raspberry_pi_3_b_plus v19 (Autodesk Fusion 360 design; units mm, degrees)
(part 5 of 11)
sketch "Sketch2" plane through (0, 0, 13.8) normal (0, 0, 1) x axis (-1, 0.0001, 0)
  line L1 (6.9604, -3.1991) -> (6.9605, -3.7992)
  line L2 (3.5604, -3.1996) -> (6.9604, -3.1991)
  line L3 (3.5605, -3.7996) -> (3.5604, -3.1996)
  line L4 (6.9605, -3.7992) -> (3.5605, -3.7996)
  line L5 (7.5605, -3.7991) -> (7.5604, -3.1991)
  line L6 (2.7854, -4.1587) -> (2.7354, -4.1587)
  line L7 (3.9604, -4.0649) -> (3.9604, -4.1089)
  line L8 (2.1854, -4.1587) -> (1.4604, -4.1587)
  line L9 (2.9747, -4.2241) -> (2.8668, -4.176)
  line L10 (3.8604, -4.2089) -> (3.528, -4.2089)
  line L11 (3.4515, -4.2241) -> (2.9747, -4.2241)
  line L12 (1.4604, -4.1587) -> (1.4604, -2.8394)
  line L13 (7.5604, -3.4991) -> (1.4604, -3.4991)
  line L14 (6.9605, -3.7992) -> (3.5605, -3.7996)
  line L15 (2.1854, -2.8394) -> (1.4604, -2.8394)
  line L16 (2.7854, -2.8394) -> (2.7354, -2.8394)
  line L17 (2.9747, -2.7741) -> (2.8668, -2.8221)
  line L18 (3.4515, -2.7741) -> (2.9747, -2.7741)
  line L19 (3.8604, -2.7893) -> (3.528, -2.7893)
  line L20 (3.9604, -2.9332) -> (3.9604, -2.8893)
  line L21 (1.3604, -4.1319) -> (1.0901, -3.9759)
  line L22 (1.4604, -4.1587) -> (1.4604, -4.1587)
  line L23 (0.45, -3.9491) -> (0.9901, -3.9491)
  line L24 (1.3604, -2.8662) -> (1.0901, -3.0223)
  line L25 (0.9901, -3.9491) -> (0.9901, -3.0491)
  line L26 (3.5605, -3.7996) -> (3.5604, -3.1996)
  line L27 (0.8339, -4.1587) -> (1.4604, -4.1587)
  line L28 (0.8339, -2.8339) -> (0.8339, -4.1587)
  line L29 (1.4604, -2.8394) -> (0.8339, -2.8339)
  arc A1 centre (3.528, -4.4089) radius 0.2 clockwise from (3.4515, -4.2241) to (3.528, -4.2089)
  arc A2 centre (4.2269, -3.6495) radius 0.15 clockwise from (4.2269, -3.7995) to (4.1436, -3.7743)
  arc A3 centre (4.0604, -3.8991) radius 0.15 clockwise from (3.9354, -3.982) to (4.1436, -3.7743)
  arc A4 centre (3.8104, -4.0649) radius 0.15 clockwise from (3.9354, -3.982) to (3.9604, -4.0649)
  arc A5 centre (3.8604, -4.1089) radius 0.1 clockwise from (3.9604, -4.1089) to (3.8604, -4.2089)
  arc A6 centre (2.7854, -4.3587) radius 0.2 clockwise from (2.7854, -4.1587) to (2.8668, -4.176)
  arc A7 centre (2.7354, -4.3587) radius 0.2 clockwise from (2.5979, -4.2135) to (2.7354, -4.1587)
  arc A8 centre (2.4604, -4.0683) radius 0.2 clockwise from (2.5979, -4.2135) to (2.3229, -4.2135)
  arc A9 centre (2.1854, -4.3587) radius 0.2 clockwise from (2.1854, -4.1587) to (2.3229, -4.2135)
  arc A10 centre (2.1854, -2.6394) radius 0.2 clockwise from (2.3229, -2.7847) to (2.1854, -2.8394)
  arc A11 centre (2.7354, -2.6394) radius 0.2 clockwise from (2.7354, -2.8394) to (2.5979, -2.7847)
  arc A12 centre (2.7854, -2.6394) radius 0.2 clockwise from (2.8668, -2.8221) to (2.7854, -2.8394)
  arc A13 centre (3.528, -2.5893) radius 0.2 clockwise from (3.528, -2.7893) to (3.4515, -2.7741)
  arc A14 centre (3.8604, -2.8893) radius 0.1 clockwise from (3.8604, -2.7893) to (3.9604, -2.8893)
  arc A15 centre (3.8104, -2.9332) radius 0.15 clockwise from (3.9604, -2.9332) to (3.9354, -3.0162)
  arc A16 centre (4.0604, -3.0991) radius 0.15 clockwise from (4.1436, -3.2239) to (3.9354, -3.0162)
  arc A17 centre (4.2269, -3.3487) radius 0.15 clockwise from (4.1436, -3.2239) to (4.2269, -3.1987)
  arc A18 centre (2.4604, -2.9299) radius 0.2 clockwise from (2.3229, -2.7847) to (2.5979, -2.7847)
  arc A19 centre (1.4604, -3.9587) radius 0.2 clockwise from (1.4604, -4.1587) to (1.3604, -4.1319)
  arc A20 centre (0.9901, -4.1491) radius 0.2 clockwise from (0.9901, -3.9491) to (1.0901, -3.9759)
  arc A21 centre (0.9901, -2.8491) radius 0.2 clockwise from (1.0901, -3.0223) to (0.9901, -3.0491)
  arc A22 centre (1.4604, -3.0394) radius 0.2 clockwise from (1.3604, -2.8662) to (1.4604, -2.8394)
  point P32 (2.7604, -4.1587)
  point P35 (1.4604, -3.4991)
  point P33 (2.3229, -4.2135)
  point P37 (2.3229, -4.2135)
  point P36 (7.5604, -3.4991)
  point P11 (4.2269, -3.7995)
  point P22 (1.4604, -4.1587)
  point P38 (1.4604, -4.1587)
  point P9 (4.1436, -3.7743)
  point P62 (4.1436, -3.2239)
  point P10 (3.9604, -4.1089)
  point P57 (3.9604, -2.8893)
  point P64 (4.2269, -3.1987)
  point P12 (3.4515, -4.2241)
  point P52 (3.4515, -2.7741)
  point P13 (3.528, -4.2089)
  point P54 (3.528, -2.7893)
  point P14 (2.8668, -4.176)
  point P50 (2.8668, -2.8221)
  point P16 (3.8604, -4.2089)
  point P55 (3.8604, -2.7893)
  point P17 (3.9354, -3.982)
  point P60 (3.9354, -3.0162)
  point P18 (2.9747, -4.2241)
  point P51 (2.9747, -2.7741)
  point P19 (3.9604, -4.0649)
  point P58 (3.9604, -2.9332)
  point P20 (2.7854, -4.1587)
  point P48 (2.7854, -2.8394)
  point P21 (2.7354, -4.1587)
  point P46 (2.7354, -2.8394)
  point P41 (1.4604, -2.8394)
  point P23 (2.1854, -4.1587)
  point P42 (2.1854, -2.8394)
  point P29 (2.5979, -4.2135)
  point P47 (2.5979, -2.7847)
  point P44 (2.3229, -2.7847)
  point P66 (2.3229, -2.7847)
  point P8 (1.4604, -2.8394)
  point P78 (1.4604, -2.8394)
  point P67 (1.3604, -4.1319)
  point P76 (1.3604, -2.8662)
  point P69 (0.9901, -3.9491)
  point P75 (0.9901, -3.0491)
  point P71 (1.0901, -3.9759)
  point P74 (1.0901, -3.0223)
  point P25 (4.0604, -3.8991)
  point P31 (2.4604, -4.0683)
  horizontal L8
  horizontal L11
  horizontal L10
  vertical L7
  vertical L12
  tangent A2 A3
  tangent A3 A4
  tangent L7 A4
  tangent L7 A5
  tangent A1 L10
  tangent L10 A5
  horizontal L6
  tangent L9 A6
  tangent L6 A6
  tangent L6 A7
  tangent A7 A8
  midpoint L6 P32
  tangent L8 A9
  collinear L6 L8
  midpoint L12 P35
  horizontal L13
  coincident P33 P37
  tangent A8 A9
  midpoint L5 P36
  coincident L4 P11
  tangent L4 A2
  coincident P22 P38
  symmetric P9 L13 P62
  symmetric P10 L13 P57
  symmetric P11 L13 P64
  symmetric P12 L13 P52
  symmetric P13 L13 P54
  symmetric P14 L13 P50
  symmetric P16 L13 P55
  symmetric P17 L13 P60
  symmetric P18 L13 P51
  symmetric P19 L13 P58
  symmetric P20 L13 P48
  symmetric P21 L13 P46
  symmetric P22 L13 P41
  symmetric P23 L13 P42
  symmetric A1 L13 A13
  symmetric A2 L13 A17
  symmetric A3 L13 A16
  symmetric A4 L13 A15
  symmetric A5 L13 A14
  symmetric A6 L13 A12
  symmetric P29 L13 P47
  symmetric A7 L13 A11
  symmetric A8 L13 A18
  symmetric P33 L13 P44
  symmetric A9 L13 A10
  symmetric L13 P37 P66
  coincident P8 P41
  perpendicular L12 L22
  tangent L8 A19
  horizontal L23
  tangent L21 A19
  tangent L21 A20
  equal A19 A20
  tangent L23 A20
  symmetric P22 L13 P78
  symmetric L13 P67 P76
  symmetric L13 A19 A22
  symmetric L13 P69 P75
  symmetric L13 P71 P74
  symmetric L13 A20 A21
  horizontal L27
  perpendicular L27 L28
  dimension "d304_1" = 0.15
  dimension "d305_1" radius A3 = 0.15
  dimension "d306_1" radius A4 = 0.15
  dimension "d307_1" radius A5 = 0.1
  dimension "d308_1" radius A1 = 0.2
  dimension "d309_1" angle L9 L11 = 24
  dimension "d310_1" distance L7 P32 = 1.2
  dimension "d311" radius A6 = 0.2
  dimension "d312_1" radius A7 = 0.2
  dimension "d313_1" radius A8 = 0.2
  dimension "d314_1" distance P20 P21 = 0.05
  dimension "d316_1" distance L8 L13 = 0.6597
  dimension "d317_1" distance P25 L13 = 0.4
  dimension "d319_1" distance L10 L13 = 0.7098
  dimension "d321_1" radius A9 = 0.2
  dimension "d323_1" distance L11 L13 = 0.725
  dimension "d326_1" distance P25 P36 = 3.5
  dimension "d327_1" distance L7 P31 = 1.5
  dimension "d328_1" distance P10 P22 = 2.5
  dimension "d329_1" distance L7 P25 = 0.1
  dimension "d331_1" distance L13 L23 = 0.45
  dimension "d334_1" angle L13 L21 = 30
  dimension "d336_1" radius A19 = 0.2
extrude "Extrude1" cut sketch "Sketch2" profile of L2 L4 A2 A3 L14 A16 A17 against normal blind 0.45 named "d338_1"
extrude "Extrude2" add sketch "Sketch2" profile of L2 L4 L6 A1 L7 L8 L9 L10 L11 L12 A3 A4 A5 A6 A7 A8 A9 L14 L15 A10 A11 L16 A12 L17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 against normal blind 0.3 named "d340_1"
face "EdgeFlange3" FlangeHeight 0.43 named "d342_1" FlangeAngle 20 named "d343_1"
step "Unfold1"
extrude "Extrude3" cut sketch "Sketch2" profile of L21 A19 A20 A21 L24 A22 L25 L27 L28 L29 no distance stored
step "Refold1"
face "EdgeFlange4" FlangeHeight 5.5 named "d345_1" FlangeAngle 0 named "d346_1"
face "EdgeFlange5" FlangeHeight 1.5 named "d347_1" FlangeAngle 45 named "d348_1"
face "EdgeFlange6" FlangeHeight 0.4 named "d349_1" FlangeAngle 65 named "d350_1"
face "EdgeFlange7" FlangeHeight 1.25 named "d351_1" FlangeAngle 85 named "d352_1"
rectangular_pattern "R-Pattern1" uSpaceDistance -2.5 named "d355_1" vSpaceDistance 0 named "d356_1"
rectangular_pattern "R-Pattern2" uSpaceDistance -7 named "d359_1" vSpaceDistance 0 named "d360_1"
rectangular_pattern "R-Pattern3" uSpaceDistance -2 named "d363_1" vSpaceDistance 0 named "d364_1"
work_plane "WorkPlane1" AlongDistance -13.14 (= "-10.28 mm - 2.71 mm - 0.15 mm") named "d288_1"
sketch "Sketch1" plane through (-4.64, 0, 15.975) normal (1, 0, 0) x axis (0, 1, 0)
  line L1 (3.8, -18.275) -> (3.598, -18.775)
  line L2 (3.8, -10.805) -> (3.8, -14.225)
  line L3 (3.2, -14.225) -> (3.2, -10.805)
  line L4 (3.8, -14.725) -> (3.8, -18.275)
  line L5 (3.2, -18.275) -> (3.2, -14.725)
  line L6 (3.2, -10.805) -> (3.8, -10.805)
  line L7 (3.598, -18.775) -> (3.402, -18.775)
  line L8 (3.402, -18.775) -> (3.2, -18.275)
  line L9 (3.7701, -0.925) -> (-3.7701, -0.925)
  line L10 (3.5, -18.775) -> (3.5, -10.805)
  line L11 (3.2, -14.475) -> (3.9, -14.475)
  line L12 (-5.95, -14.675) -> (-0.05, -14.675)
  line L13 (3.9, -14.225) -> (3.8, -14.225)
  line L14 (3.9, -14.725) -> (3.9, -14.225)
  line L15 (3.8, -14.725) -> (3.9, -14.725)
  line L16 (3.1, -14.725) -> (3.1, -14.225)
  line L17 (3.1, -14.225) -> (3.2, -14.225)
  line L18 (3.2, -14.725) -> (3.1, -14.725)
  point P16 (3.5, -10.805)
  point P17 (3.5, -18.775)
  point P8 (3.8, -18.275)
  point P12 (3.2, -18.275)
  point P6 (3.9, -14.475)
  point P10 (3.8, -14.725)
  point P26 (3.2, -14.725)
  point P11 (3.8, -14.225)
  point P25 (3.2, -14.225)
  point P21 (3.9, -14.225)
  point P23 (3.1, -14.225)
  point P22 (3.9, -14.725)
  point P24 (3.1, -14.725)
  point P4 (3.2, -14.225)
  point P9 (3.2, -14.725)
  point P15 (0, -15.975)
  point P1 (0, 0)
  vertical L3
  vertical L2
  collinear L2 L4
  collinear L3 L5
  horizontal L7
  horizontal L6
  midpoint L6 P16
  midpoint L7 P17
  horizontal L11
  symmetric P8 P12 L10
  perpendicular L2 L13
  perpendicular L13 L14
  horizontal L15
  midpoint P6 L14
  symmetric P10 L10 P26
  symmetric P11 L10 P25
  symmetric L10 P21 P23
  symmetric L10 P22 P24
  coincident P4 P25
  coincident P9 P26
  dimension "d289_1" distance L2 L3 = 0.6
  dimension "d295_1" distance L7 P15 = 2.8
  dimension "d300_1" distance P15 L11 = 1.5
  dimension "d301_1" distance P1 L10 = 3.5 (= "( 7 / 2 ) * 1 mm")
  dimension "d365_1" distance L6 L12 = 3.87 (= "5.12 mm - 1.25 mm")
  dimension "d366_1" angle L1 L4 = 22
  dimension "d367_1" distance P8 L7 = 0.5
  dimension "d368_1" distance P21 P22 = 0.5
  dimension "d369_1" distance L2 L14 = 0.1
face "Face1" sketch "Sketch1"
face "EdgeFlange2" FlangeHeight 1.5 named "d302_1" FlangeAngle 90 named "d303_1"
sketch "Sketch2" plane through (0, 0, 5.17) normal (0, 0, 1) x axis (-1, 0.0001, 0)
  line L1 (4.3404, -3.1995) -> (4.3405, -3.7995)
  line L2 (3.4404, -3.1996) -> (4.3404, -3.1995)
  line L3 (3.4405, -3.7996) -> (3.4404, -3.1996)
  line L4 (4.3405, -3.7995) -> (3.4405, -3.7996)
  line L5 (4.9405, -3.7994) -> (4.9404, -3.1994)
  line L6 (2.7854, -4.1591) -> (2.7354, -4.1591)
  line L7 (3.9604, -4.0652) -> (3.9604, -4.1092)
  line L8 (2.1854, -4.1591) -> (1.4604, -4.1591)
  line L9 (2.9747, -4.2244) -> (2.8668, -4.1763)
  line L10 (3.8604, -4.2092) -> (3.5269, -4.2092)
  line L11 (3.4504, -4.2244) -> (2.9747, -4.2244)
  line L12 (1.4604, -4.1591) -> (1.4604, -2.8397)
  line L13 (4.9404, -3.4994) -> (1.4604, -3.4994)
  line L14 (4.3405, -3.7995) -> (3.4405, -3.7996)
  line L15 (2.1854, -2.8397) -> (1.4604, -2.8397)
  line L16 (2.7854, -2.8397) -> (2.7354, -2.8397)
  line L17 (2.9747, -2.7744) -> (2.8668, -2.8224)
  line L18 (3.4504, -2.7744) -> (2.9747, -2.7744)
  line L19 (3.8604, -2.7896) -> (3.5269, -2.7896)
  line L20 (3.9604, -2.9336) -> (3.9604, -2.8896)
  line L21 (1.3604, -4.1323) -> (1.0901, -3.9762)
  line L22 (1.4604, -4.1591) -> (1.4604, -4.1591)
  line L23 (-2.17, -3.9494) -> (0.9901, -3.9494)
  line L24 (1.3604, -2.8665) -> (1.0901, -3.0226)
  line L25 (0.9901, -3.9494) -> (0.9901, -3.0494)
  line L26 (3.4405, -3.7996) -> (3.4404, -3.1996)
  line L27 (0.9604, -4.1591) -> (1.4604, -4.1591)
  line L28 (0.9604, -2.8353) -> (0.9604, -4.1591)
  line L29 (1.4604, -2.8397) -> (0.9604, -2.8353)
  arc A1 centre (3.5269, -4.4092) radius 0.2 clockwise from (3.4504, -4.2244) to (3.5269, -4.2092)
  arc A2 centre (4.2264, -3.6495) radius 0.15 clockwise from (4.2264, -3.7995) to (4.1434, -3.7744)
  arc A3 centre (4.0604, -3.8994) radius 0.15 clockwise from (3.9354, -3.9823) to (4.1434, -3.7744)
  arc A4 centre (3.8104, -4.0652) radius 0.15 clockwise from (3.9354, -3.9823) to (3.9604, -4.0652)
  arc A5 centre (3.8604, -4.1092) radius 0.1 clockwise from (3.9604, -4.1092) to (3.8604, -4.2092)
  arc A6 centre (2.7854, -4.3591) radius 0.2 clockwise from (2.7854, -4.1591) to (2.8668, -4.1763)
  arc A7 centre (2.7354, -4.3591) radius 0.2 clockwise from (2.5979, -4.2138) to (2.7354, -4.1591)
  arc A8 centre (2.4604, -4.0686) radius 0.2 clockwise from (2.5979, -4.2138) to (2.3229, -4.2138)
  arc A9 centre (2.1854, -4.3591) radius 0.2 clockwise from (2.1854, -4.1591) to (2.3229, -4.2138)
  arc A10 centre (2.1854, -2.6397) radius 0.2 clockwise from (2.3229, -2.785) to (2.1854, -2.8397)
  arc A11 centre (2.7354, -2.6397) radius 0.2 clockwise from (2.7354, -2.8397) to (2.5979, -2.785)
  arc A12 centre (2.7854, -2.6397) radius 0.2 clockwise from (2.8668, -2.8224) to (2.7854, -2.8397)
  arc A13 centre (3.5269, -2.5896) radius 0.2 clockwise from (3.5269, -2.7896) to (3.4504, -2.7744)
  arc A14 centre (3.8604, -2.8896) radius 0.1 clockwise from (3.8604, -2.7896) to (3.9604, -2.8896)
  arc A15 centre (3.8104, -2.9336) radius 0.15 clockwise from (3.9604, -2.9336) to (3.9354, -3.0165)
  arc A16 centre (4.0604, -3.0994) radius 0.15 clockwise from (4.1434, -3.2244) to (3.9354, -3.0165)
  arc A17 centre (4.2264, -3.3493) radius 0.15 clockwise from (4.1434, -3.2244) to (4.2264, -3.1993)
  arc A18 centre (2.4604, -2.9302) radius 0.2 clockwise from (2.3229, -2.785) to (2.5979, -2.785)
  arc A19 centre (1.4604, -3.9591) radius 0.2 clockwise from (1.4604, -4.1591) to (1.3604, -4.1323)
  arc A20 centre (0.9901, -4.1494) radius 0.2 clockwise from (0.9901, -3.9494) to (1.0901, -3.9762)
  arc A21 centre (0.9901, -2.8494) radius 0.2 clockwise from (1.0901, -3.0226) to (0.9901, -3.0494)
  arc A22 centre (1.4604, -3.0397) radius 0.2 clockwise from (1.3604, -2.8665) to (1.4604, -2.8397)
  point P32 (2.7604, -4.1591)
  point P35 (1.4604, -3.4994)
  point P33 (2.3229, -4.2138)
  point P37 (2.3229, -4.2138)
  point P36 (4.9404, -3.4994)
  point P22 (1.4604, -4.1591)
  point P38 (1.4604, -4.1591)
  point P9 (4.1434, -3.7744)
  point P62 (4.1434, -3.2244)
  point P10 (3.9604, -4.1092)
  point P57 (3.9604, -2.8896)
  point P12 (3.4504, -4.2244)
  point P52 (3.4504, -2.7744)
  point P13 (3.5269, -4.2092)
  point P54 (3.5269, -2.7896)
  point P14 (2.8668, -4.1763)
  point P50 (2.8668, -2.8224)
  point P16 (3.8604, -4.2092)
  point P55 (3.8604, -2.7896)
  point P17 (3.9354, -3.9823)
  point P60 (3.9354, -3.0165)
  point P18 (2.9747, -4.2244)
  point P51 (2.9747, -2.7744)
  point P19 (3.9604, -4.0652)
  point P58 (3.9604, -2.9336)
  point P20 (2.7854, -4.1591)
  point P48 (2.7854, -2.8397)
  point P21 (2.7354, -4.1591)
  point P46 (2.7354, -2.8397)
  point P41 (1.4604, -2.8397)
  point P23 (2.1854, -4.1591)
  point P42 (2.1854, -2.8397)
  point P29 (2.5979, -4.2138)
  point P47 (2.5979, -2.785)
  point P44 (2.3229, -2.785)
  point P66 (2.3229, -2.785)
  point P8 (1.4604, -2.8397)
  point P78 (1.4604, -2.8397)
  point P67 (1.3604, -4.1323)
  point P76 (1.3604, -2.8665)
  point P69 (0.9901, -3.9494)
  point P75 (0.9901, -3.0494)
  point P71 (1.0901, -3.9762)
  point P74 (1.0901, -3.0226)
  point P11 (4.2264, -3.7995)
  point P25 (4.0604, -3.8994)
  point P31 (2.4604, -4.0686)
  point P80 (0.9604, -4.1591)
  horizontal L8
  horizontal L11
  horizontal L10
  vertical L7
  vertical L12
  tangent A2 A3
  tangent A3 A4
  tangent L7 A4
  tangent L7 A5
  tangent A1 L10
  tangent L10 A5
  horizontal L6
  tangent L9 A6
  tangent L6 A6
  tangent L6 A7
  tangent A7 A8
  midpoint L6 P32
  tangent L8 A9
  collinear L6 L8
  midpoint L12 P35
  horizontal L13
  coincident P33 P37
  tangent A8 A9
  midpoint L5 P36
  tangent L4 A2
  coincident P22 P38
  symmetric P9 L13 P62
  symmetric P10 L13 P57
  symmetric P12 L13 P52
  symmetric P13 L13 P54
  symmetric P14 L13 P50
  symmetric P16 L13 P55
  symmetric P17 L13 P60
  symmetric P18 L13 P51
  symmetric P19 L13 P58
  symmetric P20 L13 P48
  symmetric P21 L13 P46
  symmetric P22 L13 P41
  symmetric P23 L13 P42
  symmetric A1 L13 A13
  symmetric A2 L13 A17
  symmetric A3 L13 A16
  symmetric A4 L13 A15
  symmetric A5 L13 A14
  symmetric A6 L13 A12
  symmetric P29 L13 P47
  symmetric A7 L13 A11
  symmetric A8 L13 A18
  symmetric P33 L13 P44
  symmetric A9 L13 A10
  symmetric L13 P37 P66
  coincident P8 P41
  perpendicular L12 L22
  tangent L8 A19
  horizontal L23
  tangent L21 A19
  tangent L21 A20
  equal A19 A20
  tangent L23 A20
  symmetric P22 L13 P78
  symmetric L13 P67 P76
  symmetric L13 A19 A22
  symmetric L13 P69 P75
  symmetric L13 P71 P74
  symmetric L13 A20 A21
  horizontal L27
  perpendicular L27 L28
  coincident L4 P11
  dimension "d304_1" = 0.15
  dimension "d305_1" radius A3 = 0.15
  dimension "d306_1" radius A4 = 0.15
  dimension "d307_1" radius A5 = 0.1
  dimension "d308_1" radius A1 = 0.2
  dimension "d309_1" angle L9 L11 = 24
  dimension "d310_1" distance L7 P32 = 1.2
  dimension "d311_1" radius A6 = 0.2
  dimension "d312_1" radius A7 = 0.2
  dimension "d313_1" radius A8 = 0.2
  dimension "d314_1" distance P20 P21 = 0.05
  dimension "d316_1" distance L8 L13 = 0.6597
  dimension "d317_1" distance P25 L13 = 0.4
  dimension "d319_1" distance L10 L13 = 0.7098
  dimension "d321_1" radius A9 = 0.2
  dimension "d323_1" distance L11 L13 = 0.725
  dimension "d326_1" distance P25 P36 = 0.88 (= "3.5 mm - 2.62 mm")
  dimension "d327_1" distance L7 P31 = 1.5
  dimension "d328_1" distance P10 P22 = 2.5
  dimension "d329_1" distance L7 P25 = 0.1
  dimension "d331_1" distance L13 L23 = 0.45
  dimension "d334_1" angle L13 L21 = 30
  dimension "d336_1" radius A19 = 0.2
  dimension "d370" distance P10 P12 = 0.51
  dimension "d372" distance P22 P80 = 0.5
extrude "Extrude1" cut sketch "Sketch2" profile of L2 L4 A2 A3 L14 A16 A17 against normal blind 0.45 named "d338_1"
extrude "Extrude2" add sketch "Sketch2" profile of L2 L4 L6 A1 L7 L8 L9 L10 L11 L12 A3 A4 A5 A6 A7 A8 A9 L14 L15 A10 A11 L16 A12 L17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 against normal blind 0.3 named "d340_1"
face "EdgeFlange3" FlangeHeight 0.43 named "d342_1" FlangeAngle 20 named "d343_1"
step "Unfold1"
extrude "Extrude3" cut sketch "Sketch2" profile of L21 A19 A20 A21 L24 A22 L25 L27 L28 L29 no distance stored
step "Refold1"
face "EdgeFlange4" FlangeHeight 5.5 named "d345_1" FlangeAngle 0 named "d346_1"
face "EdgeFlange5" FlangeHeight 1.5 named "d347_1" FlangeAngle 45 named "d348_1"
face "EdgeFlange6" FlangeHeight 0.4 named "d349_1" FlangeAngle 65 named "d350_1"
face "EdgeFlange7" FlangeHeight 1.25 named "d351_1" FlangeAngle 85 named "d352_1"
rectangular_pattern "R-Pattern4" uSpaceDistance -7 vSpaceDistance 0
rectangular_pattern "R-Pattern5" uSpaceDistance -2.5 named "d379_1" vSpaceDistance 0 named "d380_1"
rectangular_pattern "R-Pattern6" uSpaceDistance -2 vSpaceDistance 0
as_built_joint "As-built1"
work_plane "WorkPlane1" AlongDistance 15.35 named "d2_4"
canvas "Canvas1"
sketch "Sketch1" plane through (0, 0, 15.35) normal (0, 0, 1) x axis (1, 0, 0)
  line L1 (-8.5, -6.55) -> (8.5, -6.55)
  line L2 (8.5, 6.55) -> (-8.5, 6.55)
  line L3 (8.5, -6.55) -> (8.5, 6.55)
  line L4 (-8.5, 6.55) -> (8.5, -6.55)
  line L5 (8.5, 6.55) -> (-8.5, -6.55)
  line L6 (-10.1433, 0) -> (0, 0)
  line L7 (-8.425, 3.7701) -> (-8.425, -3.7701)
  line L8 (-8.5, -5.25) -> (-8.5, -6.55)
  line L9 (-8.5, -4.05) -> (-8.5, -5.05)
  line L10 (-8.5, 5.05) -> (-8.5, 4.05)
  line L11 (-8.5, 6.55) -> (-8.5, 5.25)
  line L12 (7.2048, 4.0111) -> (1.75, 4.875)
  line L13 (7.5, 2.3346) -> (7.5, 3.6654)
  line L14 (1.75, 3) -> (7.5, 3)
  line L15 (1.75, 1.125) -> (1.75, 4.875)
  line L16 (7.2048, 1.9889) -> (1.75, 1.125)
  line L17 (1.75, -1.125) -> (1.75, -4.875)
  line L18 (7.2048, -1.9889) -> (1.75, -1.125)
  line L19 (7.5, -2.3346) -> (7.5, -3.6654)
  line L20 (7.2048, -4.0111) -> (1.75, -4.875)
  arc A1 centre (-8.5, 5.15) radius 0.1 clockwise from (-8.5, 5.25) to (-8.5, 5.05)
  arc A2 centre (-8.5, 3.9) radius 0.15 clockwise from (-8.5, 4.05) to (-8.425, 3.7701)
  arc A3 centre (-8.5, -3.9) radius 0.15 clockwise from (-8.425, -3.7701) to (-8.5, -4.05)
  arc A4 centre (-8.5, -5.15) radius 0.1 clockwise from (-8.5, -5.05) to (-8.5, -5.25)
  arc A5 centre (7.15, 3.6654) radius 0.35 clockwise from (7.2048, 4.0111) to (7.5, 3.6654)
  arc A6 centre (7.15, 2.3346) radius 0.35 clockwise from (7.5, 2.3346) to (7.2048, 1.9889)
  arc A7 centre (7.15, -2.3346) radius 0.35 clockwise from (7.2048, -1.9889) to (7.5, -2.3346)
  arc A8 centre (7.15, -3.6654) radius 0.35 clockwise from (7.5, -3.6654) to (7.2048, -4.0111)
  point P6 (0, 0)
  point P1 (0, 0)
  point P7 (-8.5, 5.25)
  point P8 (-8.5, 5.05)
  point P9 (-8.5, 5.15)
  point P10 (-8.5, 4.05)
  point P11 (-8.5, 3.9)
  point P12 (0, 0)
  point P18 (-8.5, -5.25)
  point P17 (-8.5, -5.05)
  point P15 (-8.5, -4.05)
  point P23 (1.75, 3)
  point P21 (1.75, 4.875)
  point P25 (1.75, 1.125)
  point P24 (1.75, 1.125)
  point P26 (1.75, -4.875)
  point P27 (1.75, -1.125)
  point P28 (1.75, -3)
  point P22 (7.5, 3)
  point P29 (7.2048, 4.0111)
  point P33 (7.2048, 1.9889)
  point P42 (1.75, -4.875)
  point P35 (1.75, -1.125)
  point P41 (7.2048, -4.0111)
  point P30 (7.5, 3.6654)
  point P39 (7.5, -3.6654)
  point P32 (7.5, 2.3346)
  point P38 (7.5, -2.3346)
  point P36 (7.2048, -1.9889)
  point P4 (-8.5, 6.55)
  point P5 (8.5, 6.55)
  point P3 (-8.5, -6.55)
  perpendicular L1 L8
  parallel L1 L2
  parallel L3 L8
  horizontal L1
  coincident L4 P6
  coincident L5 P6
  coincident P1 P6
  coincident P7 L8
  coincident P8 L8
  coincident P9 L8
  coincident P10 L8
  coincident P11 L8
  coincident P1 P12
  horizontal L6
  symmetric P7 L6 P18
  symmetric P8 L6 P17
  symmetric A1 L6 A4
  symmetric P10 L6 P15
  symmetric A2 L6 A3
  collinear L8 L10
  collinear L8 L9
  collinear L10 L11
  vertical L7
  vertical L13
  vertical L15
  midpoint P23 L15
  symmetric P21 L14 P25
  coincident P24 P25
  symmetric L6 P21 P26
  symmetric L6 P24 P27
  midpoint L17 P28
  coincident L13 P22
  tangent L12 A5
  tangent L13 A5
  tangent L13 A6
  tangent L16 A6
  equal A5 A6
  symmetric L14 P29 P33
  symmetric L6 P21 P42
  symmetric L6 P25 P35
  symmetric L6 P29 P41
  symmetric L6 P30 P39
  symmetric L6 A5 A8
  symmetric L6 P32 P38
  symmetric L6 P33 P36
  symmetric L6 A6 A7
  dimension "d3_3" distance P4 P5 = 17
  dimension "d4_3" distance P3 P4 = 13.1
  dimension "d8_6" radius A1 = 0.1
  dimension "d10_4" distance L2 P9 = 1.4 (= "1.5 mm - 0.1 mm")
  dimension "d11_6" distance P9 P11 = 1.25
  dimension "d14_3" radius A2 = 0.15
  dimension "d15_3" distance L7 L10 = 0.075
  dimension "d46_4" distance L14 P28 = 6
  dimension "d48_4" angle L12 L15 = 81
  dimension "d49_4" distance P21 P24 = 3.75
  dimension "d52_5" distance L3 L13 = 1
  dimension "d69_5" radius A5 = 0.35
  dimension "d245_3" distance L13 L15 = 5.75
face "Face1" sketch "Sketch1"
face "EdgeFlange2" FlangeHeight 14.35 (= "13.75 mm + ( 0.3 * 2 ) * 1 mm") named "d16_4" FlangeAngle 90 named "d17_4"
face "EdgeFlange4" EdgeOffset_1 0 named "d27_4" EdgeOffset_2 -8.22 (= "-d3_3 + 10.28 mm - 1.5 mm") named "d28_4" FlangeHeight 6.5 (= "( 13.1 / 2 ) * 1 mm - 0.05 mm") named "d29_4" FlangeAngle 90 named "d30_6" EdgeOffset_1 -8.22 (= "d28_4") named "d31_6" EdgeOffset_2 0 named "d32_5" BendWidth 0.5 named "d33_5" BendDepth 0.25 named "d34_4" BendRemnant 0.6 named "d35_5"
extrude "Extrude8" cut sketch "Sketch1" profile of L12 L13 L15 L16 L17 A5 A6 L18 A7 L19 A8 L20 no distance stored
face "EdgeFlange3" EdgeOffset_1 -0.5 named "d18_5" EdgeOffset_2 -0.5 (= "d18_5") named "d19_4" EdgeOffset_1 -0.5 (= "d18_5") named "d20_4" EdgeOffset_2 -0.5 (= "d18_5") named "d21_4" FlangeHeight 0.95 (= "( ( 15 - 13.1 ) / 2 ) * 1 mm") named "d22_5" FlangeAngle 90 named "d23_5" EdgeOffset_1 -0.5 (= "d18_5") named "d24_5" EdgeOffset_2 -0.5 (= "d18_5") named "d25_5" EdgeOffset_1 0 named "d36_4" EdgeOffset_2 -0.5 (= "d18_5") named "d37_4" EdgeOffset_1 -0.5 (= "d18_5") named "d38_3" EdgeOffset_2 0 named "d39_3"
face "EdgeFlange5" FlangeHeight 0.97 (= "15.32 mm - d16_4") named "d40_3" FlangeAngle 0 named "d41_4"
face "EdgeFlange6" FlangeHeight 3 named "d42_4" FlangeAngle 30 named "d43_3"
face "EdgeFlange7" FlangeHeight 1.5 named "d44_6" FlangeAngle 70 named "d45_4"
face "EdgeFlange8" FlangeHeight 1 named "d53_5" FlangeAngle -7.5 named "d54_5" BendWidth 0.5 named "d55_4" BendDepth 0.4 named "d56_4" BendRemnant 0.6 named "d57_4"
sketch "Sketch5" plane through (0, -6.55, 0) normal (0, -1, 0) x axis (1, 0, 0)
  line L1 (-0.78, 0.1908) -> (-8.5, 0.1908)
  line L2 (-0.78, 1.6) -> (-0.78, 0.1908)
  line L3 (7.9, 1.6) -> (-0.28, 1.6)
  line L4 (7.9, 2.1) -> (7.9, 1.6)
  line L5 (7.9, 14.25) -> (7.9, 2.1)
  line L6 (7.9, 14.75) -> (7.9, 14.25)
  line L7 (-8.5, 14.75) -> (7.9, 14.75)
  line L8 (-8.5, 0.1908) -> (-8.5, 14.75)
  line L9 (-5.5966, 8.175) -> (7.9, 8.175)
  line L10 (1.8477, 5.1467) -> (6.8739, 5.675)
  line L11 (1.4, 3.7005) -> (1.4, 4.6495)
  line L12 (6.8739, 2.675) -> (1.8477, 3.2033)
  line L13 (1.4, 4.175) -> (6.9, 4.175)
  line L14 (6.9, 3.1736) -> (6.9, 5.1764)
  line L15 (1.4, 12.6495) -> (1.4, 11.7005)
  line L16 (6.8739, 13.675) -> (1.8477, 13.1467)
  line L17 (6.9, 13.1764) -> (6.9, 11.1736)
  line L18 (1.8477, 11.2033) -> (6.8739, 10.675)
  line L19 (-4.2, 11.35) -> (-2.5, 11.35)
  line L20 (-4.2, 13.05) -> (-4.2, 11.35)
  line L21 (-2.5, 13.05) -> (-4.2, 13.05)
  line L22 (-2.5, 11.35) -> (-2.5, 13.05)
  line L23 (-4.2, 13.05) -> (-2.5, 11.35)
  line L24 (-2.5, 13.05) -> (-4.2, 11.35)
  line L25 (-7.5, 7.675) -> (-6.5, 7.675)
  line L26 (-7.5, 10.675) -> (-7.5, 7.675)
  line L27 (-6.5, 10.675) -> (-7.5, 10.675)
  line L28 (-6.5, 7.675) -> (-6.5, 10.675)
  line L29 (-7.5, 10.675) -> (-6.5, 7.675)
  line L30 (-6.5, 10.675) -> (-7.5, 7.675)
  line L31 (7.9, 15.35) -> (-8.5, 15.35)
  line L32 (-4.225, 7.55) -> (3.125, 7.55)
  line L33 (-4.225, 8.8) -> (-4.225, 7.55)
  line L34 (3.125, 8.8) -> (-4.225, 8.8)
  line L35 (3.125, 7.55) -> (3.125, 8.8)
  line L36 (-4.225, 8.8) -> (3.125, 7.55)
  line L37 (3.125, 8.8) -> (-4.225, 7.55)
  line L38 (-4.2, 3.3) -> (-4.2, 5)
  line L39 (-2.5, 3.3) -> (-4.2, 3.3)
  line L40 (-2.5, 5) -> (-2.5, 3.3)
  line L41 (-4.2, 5) -> (-2.5, 5)
  line L42 (-8, 3.425) -> (-8, 4.925)
  line L43 (-8.5, 4.175) -> (-8, 4.175)
  arc A1 centre (-0.53, 1.6) radius 0.25 clockwise from (-0.78, 1.6) to (-0.28, 1.6)
  arc A2 centre (1.9, 4.6495) radius 0.5 clockwise from (1.4, 4.6495) to (1.8477, 5.1467)
  arc A3 centre (1.9, 3.7005) radius 0.5 clockwise from (1.8477, 3.2033) to (1.4, 3.7005)
  arc A4 centre (6.9, 2.9236) radius 0.25 clockwise from (6.9, 3.1736) to (6.8739, 2.675)
  arc A5 centre (6.9, 5.4264) radius 0.25 clockwise from (6.8739, 5.675) to (6.9, 5.1764)
  arc A6 centre (1.9, 12.6495) radius 0.5 clockwise from (1.4, 12.6495) to (1.8477, 13.1467)
  arc A7 centre (6.9, 13.4264) radius 0.25 clockwise from (6.8739, 13.675) to (6.9, 13.1764)
  arc A8 centre (6.9, 10.9236) radius 0.25 clockwise from (6.9, 11.1736) to (6.8739, 10.675)
  arc A9 centre (1.9, 11.7005) radius 0.5 clockwise from (1.8477, 11.2033) to (1.4, 11.7005)
  arc A10 centre (-8.25, 3.425) radius 0.25 clockwise from (-8, 3.425) to (-8.25, 3.175)
  arc A11 centre (-8.25, 2.925) radius 0.25 clockwise from (-8.5, 2.925) to (-8.25, 3.175)
  arc A12 centre (-8.25, 4.925) radius 0.25 clockwise from (-8.25, 5.175) to (-8, 4.925)
  arc A13 centre (-8.25, 5.425) radius 0.25 clockwise from (-8.25, 5.175) to (-8.5, 5.425)
  arc A14 centre (-7.35, 10.525) radius 0.15 clockwise from (-7.5, 10.525) to (-7.35, 10.675)
  arc A15 centre (-7.35, 7.825) radius 0.15 clockwise from (-7.35, 7.675) to (-7.5, 7.825)
  arc A16 centre (-6.65, 7.825) radius 0.15 clockwise from (-6.5, 7.825) to (-6.65, 7.675)
  arc A17 centre (-6.65, 10.525) radius 0.15 clockwise from (-6.65, 10.675) to (-6.5, 10.525)
  point P14 (7.9, 8.175)
  point P21 (1.4, 4.175)
  point P20 (6.9, 4.175)
  point P27 (6.9, 5.4264)
  point P26 (6.9, 2.9236)
  point P12 (6.8739, 5.675)
  point P37 (6.8739, 10.675)
  point P13 (6.8739, 2.675)
  point P32 (6.8739, 13.675)
  point P16 (1.8477, 5.1467)
  point P38 (1.8477, 11.2033)
  point P17 (1.4, 4.6495)
  point P28 (1.4, 11.7005)
  point P18 (1.4, 3.7005)
  point P29 (1.4, 12.6495)
  point P19 (1.8477, 3.2033)
  point P31 (1.8477, 13.1467)
  point P22 (6.9, 5.1764)
  point P35 (6.9, 11.1736)
  point P23 (6.9, 3.1736)
  point P34 (6.9, 13.1764)
  point P44 (-3.35, 12.2)
  point P49 (-7, 9.175)
  point P56 (-0.55, 8.175)
  point P57 (-0.3, 14.75)
  point P40 (-2.5, 11.35)
  point P61 (-2.5, 5)
  point P41 (-4.2, 11.35)
  point P58 (-4.2, 5)
  point P42 (-4.2, 13.05)
  point P59 (-4.2, 3.3)
  point P43 (-2.5, 13.05)
  point P60 (-2.5, 3.3)
  point P66 (-8.5, 2.925)
  point P70 (-8.5, 5.425)
  point P72 (-8, 4.175)
  point P73 (-8.5, 4.175)
  point P69 (-8.25, 4.925)
  point P71 (-8.25, 5.425)
  point P75 (-7.35, 10.675)
  point P74 (-7.5, 10.525)
  point P78 (-7.35, 7.675)
  point P77 (-7.5, 7.825)
  point P81 (-6.5, 7.825)
  point P80 (-6.65, 7.675)
  point P84 (-6.65, 10.675)
  point P83 (-6.5, 10.525)
  point P46 (-7.5, 7.675)
  point P47 (-7.5, 10.675)
  point P48 (-6.5, 10.675)
  point P54 (-4.225, 8.8)
  point P55 (3.125, 8.8)
  point P53 (-4.225, 7.55)
  point P62 (-8, 4.925)
  point P63 (-8, 3.425)
  midpoint L5 P14
  horizontal L9
  midpoint L11 P21
  horizontal L13
  vertical L14
  midpoint P20 L14
  tangent L11 A2
  tangent L11 A3
  tangent L10 A2
  tangent L12 A3
  tangent L12 A4
  tangent L10 A5
  vertical L11
  equal A2 A3
  coincident L14 P27
  coincident L14 P26
  equal A4 A5
  symmetric P12 L9 P37
  symmetric P13 L9 P32
  symmetric L9 P16 P38
  symmetric L9 P17 P28
  symmetric L9 P18 P29
  symmetric L9 P19 P31
  symmetric L9 P22 P35
  symmetric L9 P23 P34
  symmetric L9 A2 A9
  symmetric L9 A3 A6
  symmetric L9 A4 A7
  symmetric L9 A5 A8
  perpendicular L19 L20
  parallel L19 L21
  parallel L20 L22
  horizontal L19
  coincident L23 P44
  coincident L24 P44
  perpendicular L25 L26
  parallel L25 L27
  parallel L26 L28
  horizontal L25
  coincident L29 P49
  coincident L30 P49
  perpendicular L32 L33
  parallel L32 L34
  parallel L33 L35
  horizontal L32
  coincident L36 P56
  coincident L37 P56
  coincident L9 P56
  midpoint L7 P57
  symmetric L9 P40 P61
  symmetric L9 P41 P58
  symmetric L9 P42 P59
  symmetric L9 P43 P60
  tangent L42 A10
  coincident L8 P66
  tangent A10 A11
  vertical L42
  tangent L42 A12
  coincident L8 P70
  tangent A12 A13
  tangent L8 A13
  tangent L8 A11
  midpoint L42 P72
  coincident L8 P73
  horizontal L43
  equal A12 A13
  equal A10 A12
  equal A10 A11
  vertical P69 P71
  tangent L27 A14
  coincident L27 P75
  coincident L26 P74
  tangent L25 A15
  coincident L25 P78
  coincident L26 P77
  tangent L28 A16
  coincident L28 P81
  coincident L25 P80
  tangent L28 A17
  coincident L27 P84
  coincident L28 P83
  tangent L27 A17
  tangent L26 A14
  tangent L26 A15
  tangent L25 A16
  equal A14 A17
  equal A16 A17
  equal A15 A16
  dimension "d120_2" distance P12 P13 = 3
  dimension "d123_2" distance L9 L13 = 4
  dimension "d124_3" radius A2 = 0.5
  dimension "d125_3" radius A4 = 0.25
  dimension "d126_3" angle L10 L14 = 84
  dimension "d127_3" distance L11 L14 = 5.5
  dimension "d128_3" distance L5 L14 = 1
  dimension "d176_2" distance P42 P43 = 1.7 (= "2 mm - d1_4")
  dimension "d177_2" distance P41 P42 = 1.7
  dimension "d178_2" distance P46 P47 = 3
  dimension "d179_2" distance P47 P48 = 1
  dimension "d180_2" distance L8 L20 = 4.3 (= "4 mm + d1_4")
  dimension "d181_2" distance L8 L26 = 1
  dimension "d182_2" distance L21 L31 = 2.3 (= "2 mm + d1_4")
  dimension "d183_2" distance P54 P55 = 7.35
  dimension "d184_2" distance P53 P54 = 1.25
  dimension "d185_1" distance P56 P57 = 0.25
  dimension "d187_2" distance P62 P63 = 1.5
  dimension "d189_2" distance L8 L42 = 0.5
  dimension "d190_2" distance L9 L43 = 4
  dimension "d198_1" radius A17 = 0.15 (= "d1_4 / 2")
  dimension "d223_3" distance L9 P49 = 1
extrude "Extrude7" cut sketch "Sketch5" profile of L8 L10 L11 L12 L14 A2 A3 A4 A5 L15 A6 L16 A7 L17 A8 L18 A9 L19 L20 L21 L22 L25 L26 L27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 no distance stored
face "EdgeFlange11" FlangeHeight 3.6 named "d130_3" FlangeAngle 10 named "d131_3"
step "Unfold1"
sketch "Sketch3" plane through (0, 0, 15.35) normal (0, 0, 1) x axis (-1, 0, 0)
  line L1 (-1.7869, -1.625) -> (-1.7869, -4.375)
  line L2 (-7, -3.5135) -> (-1.5412, -4.3781)
  line L3 (-7, -2.4865) -> (-7, -3.5135)
  line L4 (-1.5412, -1.6219) -> (-7, -2.4865)
  line L5 (-1.7303, -1.625) -> (-1.7303, -4.375)
  line L6 (-7.5, -2.3346) -> (-7.5, -3.6654)
  line L7 (-7.2048, -4.0111) -> (-2, -4.8354)
  line L8 (-2, -1.1646) -> (-7.2048, -1.9889)
  line L9 (-2, -4.8354) -> (-1.75, -4.875)
  line L10 (-1.5803, -4.875) -> (-2, -4.875)
  line L11 (-2, -4.875) -> (-1.5803, -4.875)
  line L12 (-1.75, -1.125) -> (-2, -1.1646)
  line L13 (-1.5803, -1.125) -> (-2, -1.125)
  line L14 (-2, -1.125) -> (-2, -1.1646)
  line L15 (-2, -4.8354) -> (-2, -4.875)
  line L16 (-1.7303, 4.375) -> (-1.7303, 1.625)
  line L17 (-11.6332, 0) -> (0, 0)
  line L18 (-2, 4.875) -> (-1.5803, 4.875)
  line L19 (-2, 4.8354) -> (-2, 4.875)
  line L20 (-2, 1.125) -> (-2, 1.1646)
  line L21 (-1.5803, 1.125) -> (-2, 1.125)
  line L22 (-1.75, 1.125) -> (-2, 1.1646)
  line L23 (-2, 4.8354) -> (-1.75, 4.875)
  line L24 (-7, 3.5135) -> (-1.5412, 4.3781)
  line L25 (-7, 2.4865) -> (-7, 3.5135)
  line L26 (-1.5412, 1.6219) -> (-7, 2.4865)
  line L27 (-5, -2.1697) -> (-5, -3.8303)
  line L28 (-5, 3.8303) -> (-5, 2.1697)
  line L29 (-2.7476, 1.625) -> (-2.7476, 4.375)
  line L30 (-2.7476, -4.375) -> (-2.7476, -1.625)
  line L31 (-7.2048, 1.9889) -> (-2, 1.1646)
  line L32 (-7.5, 3.6654) -> (-7.5, 2.3346)
  line L33 (-2, 4.8354) -> (-7.2048, 4.0111)
  line L34 (-2.0343, 16.7136) -> (-6.9525, 16.1966)
  line L35 (-1.9, 17.5444) -> (-1.9, 16.8627)
  line L36 (-6.9525, 18.2105) -> (-2.0343, 17.6936)
  line L37 (-6.9525, 18.2105) -> (-6.9525, 16.1966)
  line L38 (-6.9525, 17.2036) -> (-1.9, 17.2036)
  line L39 (-1.8477, 18.1753) -> (-6.8739, 18.7036)
  line L40 (-6.8739, 15.7036) -> (-1.8477, 16.2319)
  line L41 (-1.4, 16.7291) -> (-1.4, 17.6781)
  line L42 (-2.0343, -16.7136) -> (-6.9525, -16.1966)
  line L43 (-1.9, -17.5444) -> (-1.9, -16.8627)
  line L44 (-6.9525, -18.2105) -> (-2.0343, -17.6936)
  line L45 (-6.8739, -18.7036) -> (-1.8477, -18.1753)
  line L46 (-1.4, -17.6781) -> (-1.4, -16.7291)
  line L47 (-1.8477, -16.2319) -> (-6.8739, -15.7036)
  line L48 (-3.3296, -16.2022) -> (-3.3296, -18.205)
  line L49 (-7.9, 19.2786) -> (-7.9, 7.1286)
  line L50 (4.3644, 13.2036) -> (-7.9, 13.2036)
  line L51 (-2.0343, 9.6936) -> (-6.9525, 10.2105)
  line L52 (-1.9, 8.8627) -> (-1.9, 9.5444)
  line L53 (-6.9525, 8.1966) -> (-2.0343, 8.7136)
  line L54 (-6.8739, 7.7036) -> (-1.8477, 8.2319)
  line L55 (-1.4, 8.7291) -> (-1.4, 9.6781)
  line L56 (-1.8477, 10.1753) -> (-6.8739, 10.7036)
  line L57 (-1.4, -9.6781) -> (-1.4, -8.7291)
  line L58 (-6.8739, -10.7036) -> (-1.8477, -10.1753)
  line L59 (-1.8477, -8.2319) -> (-6.8739, -7.7036)
  line L60 (-2.0343, -9.6936) -> (-6.9525, -10.2105)
  line L61 (-1.9, -8.8627) -> (-1.9, -9.5444)
  line L62 (-6.9525, -8.1966) -> (-2.0343, -8.7136)
  line L63 (-2, 21.5718) -> (-2, 21.5322)
  line L64 (-7.2048, 22.3961) -> (-2, 21.5718)
  line L65 (-7.5, 24.0725) -> (-7.5, 22.7418)
  line L66 (-2, 25.2426) -> (-7.2048, 24.4182)
  line L67 (-2, 25.2822) -> (-2, 25.2426)
  line L68 (-1.5803, 25.2822) -> (-2, 25.2822)
  line L69 (-1.7303, 24.7822) -> (-1.5803, 24.7822)
  line L70 (-1.7303, 22.0322) -> (-1.7303, 24.7822)
  line L71 (-1.5803, 22.0322) -> (-1.7303, 22.0322)
  line L72 (-2, 21.5322) -> (-1.5803, 21.5322)
  line L73 (-7.9, 20.9572) -> (-7.9, 26.3572)
  line L74 (-7.9, 20.4572) -> (-7.9, 20.9572)
  line L75 (0.28, 20.4572) -> (-7.9, 20.4572)
  line L76 (0.28, 26.3572) -> (0.28, 20.4572)
  line L77 (-7.9, 26.3572) -> (0.28, 26.3572)
  line L78 (-1.7303, 23.4072) -> (-7.5, 23.4072)
  line L79 (-6.7891, 23.9541) -> (-1.5412, 24.7852)
  line L80 (-7, 23.1072) -> (-7, 23.7071)
  line L81 (-1.5412, 22.0291) -> (-6.7891, 22.8603)
  line L82 (-5, 24.2374) -> (-5, 22.5769)
  line L83 (-1.75, 25.2822) -> (-2, 25.2426)
  line L84 (-1.75, 21.5322) -> (-2, 21.5718)
  line L85 (-2.7476, 22.0322) -> (-2.7476, 24.7822)
  line L86 (-6.7891, -23.9541) -> (-1.5412, -24.7852)
  line L87 (-7, -23.1072) -> (-7, -23.7071)
  line L88 (-1.5412, -22.0291) -> (-6.7891, -22.8603)
  line L89 (-5, -24.2374) -> (-5, -22.5769)
  line L90 (-7.9, -20.9572) -> (-7.9, -20.4572)
  line L91 (-7.9, -26.3572) -> (-7.9, -20.9572)
  line L92 (0.28, -26.3572) -> (-7.9, -26.3572)
  line L93 (0.28, -20.4572) -> (0.28, -26.3572)
  line L94 (-7.9, -20.4572) -> (0.28, -20.4572)
  line L95 (-1.5803, -24.7822) -> (-1.7303, -24.7822)
  line L96 (-2, -25.2822) -> (-1.5803, -25.2822)
  line L97 (-2, -25.2426) -> (-2, -25.2822)
  line L98 (-7.2048, -24.4182) -> (-2, -25.2426)
  line L99 (-7.5, -22.7418) -> (-7.5, -24.0725)
  line L100 (-2, -21.5718) -> (-7.2048, -22.3961)
  line L101 (-2, -21.5322) -> (-2, -21.5718)
  line L102 (-1.5803, -21.5322) -> (-2, -21.5322)
  line L103 (-1.7303, -22.0322) -> (-1.5803, -22.0322)
  line L104 (-1.7303, -24.7822) -> (-1.7303, -22.0322)
  line L105 (-1.75, -25.2822) -> (-2, -25.2426)
  line L106 (-2.7476, -24.7822) -> (-2.7476, -22.0322)
  line L107 (-1.75, -21.5322) -> (-2, -21.5718)
  arc A1 centre (-1.5803, -4.625) radius 0.25 clockwise from (-1.5803, -4.375) to (-1.5803, -4.875)
  arc A2 centre (-1.5803, -4.625) radius 0.25 clockwise from (-1.5803, -4.375) to (-1.5803, -4.875)
  arc A3 centre (-1.5803, -1.375) radius 0.25 clockwise from (-1.5803, -1.125) to (-1.5803, -1.625)
  arc A4 centre (-1.5803, 4.625) radius 0.25 clockwise from (-1.5803, 4.875) to (-1.5803, 4.375)
  arc A5 centre (-1.5803, 1.375) radius 0.25 clockwise from (-1.5803, 1.625) to (-1.5803, 1.125)
  arc A6 centre (-6.75, -3.3) radius 0.25 clockwise from (-6.7891, -3.5469) to (-7, -3.3)
  arc A7 centre (-6.75, -2.7) radius 0.25 clockwise from (-7, -2.7) to (-6.7891, -2.4531)
  arc A8 centre (-6.75, 3.3) radius 0.25 clockwise from (-7, 3.3) to (-6.7891, 3.5469)
  arc A9 centre (-6.75, 2.7) radius 0.25 clockwise from (-6.7891, 2.4531) to (-7, 2.7)
  arc A10 centre (-7.15, -3.6654) radius 0.35 clockwise from (-7.2048, -4.0111) to (-7.5, -3.6654)
  arc A11 centre (-7.15, -2.3346) radius 0.35 clockwise from (-7.5, -2.3346) to (-7.2048, -1.9889)
  arc A12 centre (-7.15, 2.3346) radius 0.35 clockwise from (-7.2048, 1.9889) to (-7.5, 2.3346)
  arc A13 centre (-7.15, 3.6654) radius 0.35 clockwise from (-7.5, 3.6654) to (-7.2048, 4.0111)
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  point P10 (-1.5412, -4.3781)
  point P16 (-1.5412, -1.6219)
  point P21 (-2, -4.8354)
  point P24 (-2, -4.8354)
  point P23 (-1.75, -4.875)
  point P22 (-2, -1.1646)
  point P27 (-2, -1.1646)
  point P28 (-1.75, -1.125)
  point P1 (0, 0)
  point P33 (0, 0)
  point P4 (-1.5803, -4.875)
  point P36 (-1.5803, 4.875)
  point P5 (-1.5803, -4.375)
  point P37 (-1.5803, 4.375)
  point P47 (-1.5412, 4.3781)
  point P11 (-7, -3.5135)
  point P48 (-7, 3.5135)
  point P12 (-7, -2.4865)
  point P49 (-7, 2.4865)
  point P13 (-1.5803, -1.625)
  point P52 (-1.5803, 1.625)
  point P14 (-1.5803, -1.125)
  point P53 (-1.5803, 1.125)
  point P50 (-1.5412, 1.6219)
  point P39 (-2, 4.8354)
  point P40 (-2, 1.1646)
  point P45 (-1.75, 4.875)
  point P46 (-2, 4.8354)
  point P26 (-2, -4.875)
  point P38 (-2, 4.875)
  point P43 (-2, 1.1646)
  point P44 (-1.75, 1.125)
  point P29 (-2, -1.125)
  point P41 (-2, 1.125)
  point P30 (-1.5803, -1.125)
  point P42 (-1.5803, 1.125)
  point P54 (-5, -3.8303)
  point P55 (-5, 3.8303)
  point P56 (-5, -2.1697)
  point P57 (-5, 2.1697)
  point P63 (-7, -3.3)
  point P62 (-6.7891, -3.5469)
  point P66 (-7, -2.7)
  point P65 (-6.7891, -2.4531)
  point P70 (-6.7891, 3.5469)
  point P69 (-7, 3.3)
  point P72 (-6.7891, 2.4531)
  point P73 (-7, 2.7)
  point P90 (-6.9525, 16.1966)
  point P91 (-6.9525, 16.1966)
  point P98 (-6.9525, 18.2105)
  point P99 (-6.9525, 18.2105)
  point P102 (-1.9, 17.2036)
  point P103 (-6.9525, 17.2036)
  point P114 (-6.9525, -16.1966)
  point P92 (-2.0343, 16.7136)
  point P115 (-2.0343, -16.7136)
  point P93 (-1.9, 16.8627)
  point P117 (-1.9, -16.8627)
  point P95 (-1.9, 17.5444)
  point P118 (-1.9, -17.5444)
  point P96 (-2.0343, 17.6936)
  point P120 (-2.0343, -17.6936)
  point P121 (-6.9525, -18.2105)
  point P138 (-7.9, 13.2036)
  point P140 (-6.9525, 10.2105)
  point P141 (-2.0343, 9.6936)
  point P143 (-1.9, 9.5444)
  point P144 (-1.9, 8.8627)
  point P146 (-2.0343, 8.7136)
  point P147 (-6.9525, 8.1966)
  point P172 (-6.9525, -10.2105)
  point P173 (-2.0343, -9.6936)
  point P175 (-1.9, -9.5444)
  point P176 (-1.9, -8.8627)
  point P178 (-2.0343, -8.7136)
  point P179 (-6.9525, -8.1966)
  point P203 (-7.5, 23.4072)
  point P204 (-1.7303, 23.4072)
  point P206 (-6.7891, 23.9541)
  point P210 (-6.7891, 22.8603)
  point P213 (-5, 22.5769)
  point P214 (-5, 24.2374)
  point P188 (-2, 25.2426)
  point P215 (-2, 25.2426)
  point P216 (-1.75, 25.2822)
  point P181 (-2, 21.5718)
  point P217 (-2, 21.5718)
  point P218 (-1.75, 21.5322)
  point P205 (-1.5412, 24.7852)
  point P221 (-1.5412, -24.7852)
  point P222 (-6.7891, -23.9541)
  point P207 (-7, 23.7071)
  point P224 (-7, -23.7071)
  point P209 (-7, 23.1072)
  point P225 (-7, -23.1072)
  point P227 (-6.7891, -22.8603)
  point P212 (-1.5412, 22.0291)
  point P228 (-1.5412, -22.0291)
  point P229 (-5, -22.5769)
  point P230 (-5, -24.2374)
  point P241 (-2, -25.2426)
  point P254 (-2, -25.2426)
  point P255 (-1.75, -25.2822)
  point P248 (-2, -21.5718)
  point P258 (-2, -21.5718)
  point P259 (-1.75, -21.5322)
  coincident A1 P10
  coincident A3 P16
  tangent A3 L4
  vertical L3
  tangent A1 L2
  parallel L2 L7
  parallel L4 L8
  coincident P21 P24
  coincident P23 L10
  parallel L7 L9
  coincident P22 P27
  parallel L8 L12
  coincident P28 L13
  coincident P1 P33
  horizontal L17
  symmetric P4 L17 P36
  symmetric P5 L17 P37
  symmetric A1 L17 A4
  symmetric P10 L17 P47
  symmetric P11 L17 P48
  symmetric P12 L17 P49
  symmetric P13 L17 P52
  symmetric P14 L17 P53
  symmetric A3 L17 A5
  symmetric P16 L17 P50
  symmetric P21 L17 P39
  symmetric P22 L17 P40
  symmetric P23 L17 P45
  symmetric P24 L17 P46
  symmetric P26 L17 P38
  symmetric P27 L17 P43
  symmetric P28 L17 P44
  symmetric P29 L17 P41
  symmetric P30 L17 P42
  coincident L2 P54
  coincident L24 P55
  vertical L27
  collinear L27 L28
  coincident L4 P56
  coincident L26 P57
  tangent L2 A6
  coincident L3 P63
  coincident L2 P62
  tangent L3 A6
  tangent L4 A7
  coincident L3 P66
  coincident L4 P65
  tangent L3 A7
  equal A6 A7
  symmetric L17 P62 P70
  symmetric L17 P63 P69
  symmetric L17 A6 A8
  symmetric L17 P65 P72
  symmetric L17 P66 P73
  symmetric L17 A7 A9
  coincident P90 P91
  vertical L35
  coincident P98 P99
  midpoint L35 P102
  midpoint L37 P103
  horizontal L38
  parallel L36 L39
  parallel L34 L40
  symmetric L17 P91 P114
  symmetric L17 P92 P115
  symmetric L17 P93 P117
  symmetric L17 P95 P118
  symmetric L17 P96 P120
  symmetric L17 P99 P121
  midpoint L49 P138
  horizontal L50
  symmetric P91 L50 P140
  symmetric P92 L50 P141
  symmetric P93 L50 P143
  symmetric P95 L50 P144
  symmetric P96 L50 P146
  symmetric P99 L50 P147
  symmetric L17 P140 P172
  symmetric L17 P141 P173
  symmetric L17 P143 P175
  symmetric L17 P144 P176
  symmetric L17 P146 P178
  symmetric L17 P147 P179
  midpoint L65 P203
  midpoint L70 P204
  vertical L80
  symmetric L78 P206 P210
  coincident L81 P213
  coincident L79 P214
  vertical L82
  collinear L3 L80
  parallel L64 L81
  collinear L27 L82
  coincident P188 P215
  parallel L66 L83
  coincident L68 P216
  coincident P181 P217
  parallel L64 L84
  coincident L72 P218
  symmetric L17 P205 P221
  symmetric L17 P206 P222
  symmetric L17 P207 P224
  symmetric L17 P209 P225
  symmetric L17 P210 P227
  symmetric L17 P212 P228
  symmetric L17 P213 P229
  symmetric L17 P214 P230
  coincident P241 P254
  parallel L98 L105
  coincident L96 P255
  coincident P248 P258
  parallel L100 L107
  coincident L102 P259
  dimension "d58_3" distance L3 L6 = 0.5
  dimension "d62_3" distance L25 L27 = 2
  dimension "d67_4" radius A6 = 0.25
  dimension "d133_3" radius = 0.15
  dimension "d227_3" distance L35 L41 = 0.5
  dimension "d386_1" radius = 0.25 (= "d67_4")
extrude "Extrude1" cut sketch "Sketch3" no distance stored
extrude "Extrude2" add sketch "Sketch3" profile of L2 L4 L9 L10 L11 L12 L13 L14 L15 L18 L19 L20 L21 L22 L23 L24 L26 L28 L29 L30 L63 L67 L68 L72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 to an object
canvas "Canvas2"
